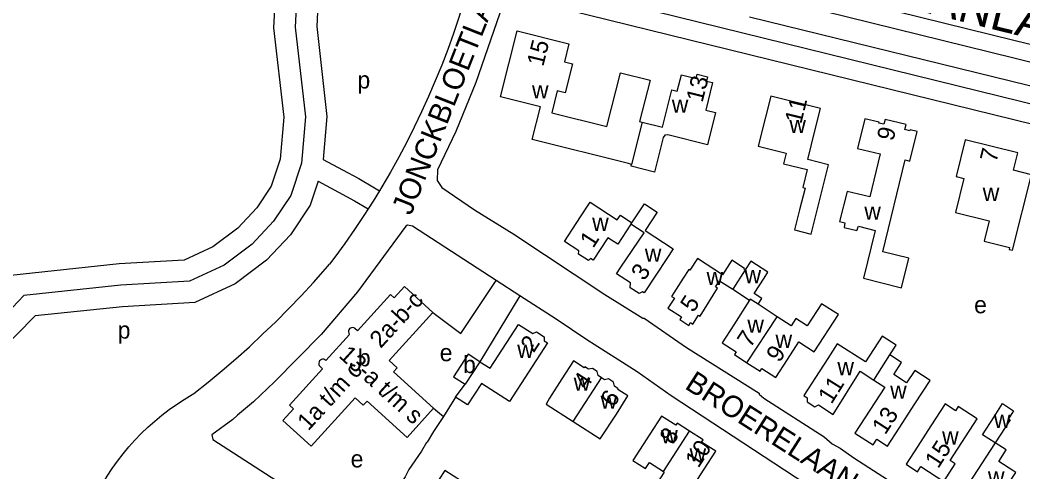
# Model space of a CAD drawing. Extents: x 161141 to 163125, y 381621 to 383200.
# Drawn here: x 161268.8 to 161502.1, y 382076.1 to 382181.3 of the extents above; entities that cross this region are included whole.
import ezdxf

# ---------------------------------------------------------------- set-up
doc = ezdxf.new("R2010")
doc.units = 0
for name, color, linetype in [('BLT_Basislijn', 7, 'Continuous'), ('BLT_Bebouwing', 7, 'Continuous'), ('BLT_Centroide', 7, 'Continuous'), ('BLT_Huisnummer', 7, 'Continuous'), ('BLT_Huisnummer_reeks', 7, 'Continuous'), ('BLT_Onderverdeling_panden', 7, 'Continuous'), ('BLT_Straatnaam', 7, 'Continuous'), ('BLT_Straatnaam_hoofdweg', 7, 'Continuous')]:
    doc.layers.add(name, color=color, linetype=linetype)

msp = doc.modelspace()

# ---------------------------------------------------------------- linework, layer by layer
at = {"layer": 'BLT_Basislijn'}
for p, q in [((161577.61, 382147.74), (161438.48, 382181.99)), ((161385.09, 382117.09), (161379.56, 382120.67)), ((161385.09, 382117.09), (161375.76, 382101.74)), ((161272.27, 382112.38), (161255.91, 382095.79)), ((161370.1, 382093.47), (161367.31, 382089)), ((161364.97, 382090.89), (161367.31, 382089))]:
    msp.add_line(p, q, dxfattribs=at)
for points in [[(161342.07, 382215.1), (161335.39, 382206.7), (161328.71, 382198.33), (161328.71, 382198.33), (161327.75, 382179.45), (161330.12, 382158.69), (161329.28, 382148.93), (161327.22, 382142.63), (161323.82, 382137.55), (161319.42, 382132.85), (161313.65, 382128.5), (161306.97, 382125.4), (161291.79, 382124.52), (161261.51, 382121.28)], [(161575.91, 382159.3), (161574.79, 382159.38), (161572.09, 382159.65), (161569.4, 382159.99), (161566.73, 382160.42), (161564.06, 382160.92), (161561.42, 382161.5), (161558.79, 382162.16), (161558.23, 382162.31), (161500, 382176.55), (161440.48, 382191.25), (161423.98, 382195.51), (161417.63, 382197.28)], [(161416.7, 382193.12), (161425.52, 382190.9), (161439.31, 382187.51), (161500, 382172.47), (161560.84, 382157.4), (161561.46, 382157.23), (161564.86, 382156.37), (161568.29, 382155.59), (161571.73, 382154.88), (161575.19, 382154.26), (161575.32, 382154.24)], [(161333.31, 382190.25), (161332.76, 382179.6), (161335.14, 382158.76), (161334.21, 382147.93), (161331.76, 382140.42), (161327.75, 382134.43), (161322.78, 382129.11), (161316.24, 382124.19), (161308.21, 382120.47), (161292.2, 382119.53), (161269.67, 382117.13)], [(161571.87, 382145), (161411.72, 382184.47), (161385.01, 382191.48)], [(161338.21, 382188.31), (161337.78, 382179.76), (161340.17, 382158.83), (161339.31, 382148.78)], [(161372.97, 382188.8), (161372.06, 382185.67), (161370.88, 382181.91), (161369.62, 382178.17), (161368.28, 382174.46), (161366.87, 382170.78), (161365.39, 382167.13), (161363.83, 382163.5), (161362.2, 382159.91), (161360.49, 382156.36), (161358.72, 382152.83), (161356.87, 382149.35), (161354.96, 382145.9), (161352.97, 382142.49), (161352.4, 382141.56)], [(161382.01, 382187.19), (161381.71, 382186.78), (161374.84, 382166.75), (161370.17, 382155.35), (161365.86, 382146.45), (161365.8, 382143.9), (161366.88, 382142.33), (161374.51, 382137.13), (161383.63, 382131.44), (161404.83, 382117.4), (161413.7, 382111.85), (161413.96, 382111.85), (161423.8, 382105.03), (161440.74, 382094.38), (161440.77, 382094.15), (161441.8, 382093.21), (161455.89, 382084.27), (161457.77, 382082.61), (161459.58, 382081.61), (161462.78, 382079.32), (161507, 382050.9), (161516.84, 382044.29), (161522.29, 382040.94)], [(161574.59, 382121.57), (161578.68, 382127.76), (161579.74, 382129.89), (161580.44, 382131.88), (161580.51, 382133.62), (161580.11, 382135.93), (161578.32, 382138.29), (161575.39, 382139.5), (161382.01, 382187.19)], [(161339.31, 382148.78), (161343.81, 382146.41), (161347.56, 382144.36), (161351.27, 382142.23), (161352.4, 382141.56)], [(161338.12, 382143.77), (161336.3, 382138.21), (161331.68, 382131.31), (161326.13, 382125.38), (161318.82, 382119.88), (161309.45, 382115.53), (161292.62, 382114.55), (161272.27, 382112.38)], [(161338.12, 382143.77), (161342.86, 382141.24), (161346.56, 382139.18), (161349.76, 382137.32)], [(161352.4, 382141.56), (161350.91, 382139.13), (161349.76, 382137.32)], [(161349.76, 382137.32), (161348.79, 382135.8), (161346.6, 382132.53), (161344.34, 382129.29), (161342.02, 382126.1), (161340.75, 382124.41)], [(161379.56, 382120.67), (161360.06, 382133.28), (161358.94, 382133.49), (161358.53, 382133.33), (161347.3, 382118.04), (161338.82, 382108.04), (161327.96, 382097.02), (161323.1, 382092.36), (161319.32, 382089.32), (161318.3, 382088.27), (161313.4, 382084.74), (161313.61, 382083.66), (161349.27, 382060.57)], [(161309.2, 382094.31), (161312.5, 382096.95), (161315.76, 382099.65), (161318.96, 382102.41), (161322.11, 382105.23), (161325.21, 382108.11), (161328.25, 382111.05), (161331.23, 382114.04), (161334.16, 382117.09), (161337.03, 382120.2), (161339.84, 382123.36), (161340.75, 382124.41)], [(161364.82, 382113.19), (161371.3, 382108.27), (161379.56, 382120.67)], [(161236.17, 382083.91), (161251.11, 382097.62), (161269.67, 382117.13)], [(161453.83, 382071.76), (161420.3, 382093.8), (161412.36, 382099.41), (161400.64, 382106.81), (161393.49, 382111.68), (161385.09, 382117.09)], [(161286.9, 382071.36), (161287.93, 382073.23), (161289.02, 382075.05), (161290.19, 382076.84), (161291.42, 382078.58), (161292.72, 382080.27), (161294.07, 382081.91), (161295.49, 382083.49), (161296.97, 382085.03), (161298.51, 382086.5), (161300.09, 382087.92), (161301.73, 382089.28), (161303.43, 382090.58), (161305.16, 382091.8), (161306.95, 382092.97), (161308.77, 382094.07), (161309.2, 382094.31)], [(161367.31, 382089), (161364.93, 382085.46), (161363.52, 382082.99), (161363.34, 382082.95), (161362.14, 382080.87), (161359.24, 382076.64), (161358.38, 382074.95), (161351.69, 382064.82), (161349.27, 382060.57)]]:
    msp.add_lwpolyline(points, dxfattribs=at)
at = {"layer": 'BLT_Bebouwing'}
for p, q in [((161380.56, 382163.42), (161384.41, 382178.79)), ((161384.41, 382178.79), (161396.49, 382175.75)), ((161396.49, 382175.75), (161395.44, 382171.57)), ((161395.44, 382171.57), (161397.31, 382171.09)), ((161397.31, 382171.09), (161395.63, 382164.36)), ((161405.33, 382156.47), (161408.49, 382169)), ((161408.49, 382169), (161415.35, 382167.3)), ((161393.77, 382164.83), (161392.48, 382159.66)), ((161395.63, 382164.36), (161393.77, 382164.83)), ((161389.84, 382161.08), (161380.56, 382163.42)), ((161387.93, 382153.49), (161389.84, 382161.08)), ((161392.48, 382159.66), (161405.33, 382156.47)), ((161413.55, 382157.51), (161418.26, 382156.31)), ((161434.58, 382118.61), (161438.51, 382116.05)), ((161437.91, 382101.5), (161444.92, 382112.21)), ((161345.44, 382108.09), (161339.92, 382102.02)), ((161373.04, 382103.5), (161369.63, 382098.24)), ((161375.76, 382101.74), (161373.04, 382103.5)), ((161369.63, 382098.24), (161372.35, 382096.48)), ((161370.1, 382093.47), (161372.35, 382096.48))]:
    msp.add_line(p, q, dxfattribs=at)
for points in [[(161415.35, 382167.3), (161412.87, 382157.68), (161413.55, 382157.51)], [(161418.26, 382156.31), (161420.44, 382165.05), (161421.69, 382164.73), (161422.65, 382168.56), (161426.09, 382167.71), (161426.33, 382168.67), (161428.73, 382168.07), (161428.48, 382167.07), (161429.91, 382166.71), (161428.32, 382160.3)], [(161451.93, 382146.47), (161450.89, 382142.29), (161451.42, 382142.16), (161450.16, 382137.07), (161449, 382132.43), (161452.88, 382131.46), (161454.04, 382136.11), (161456.89, 382147.58), (161452.05, 382148.78), (161453.81, 382155.83), (161455.01, 382160.68), (161443.43, 382163.56), (161442.23, 382158.71), (161440.53, 382151.89), (161447.05, 382150.27), (161446.44, 382147.84), (161451.93, 382146.47)], [(161428.32, 382160.3), (161430.61, 382159.73), (161428.75, 382152.27), (161419.47, 382154.58), (161418.81, 382154.48), (161418.41, 382153.95), (161416.36, 382145.89), (161410.94, 382147.27), (161411.05, 382147.69)], [(161411.05, 382147.69), (161410.33, 382147.87), (161387.93, 382153.49)], [(161400.66, 382137.73), (161401.39, 382138.86), (161407.74, 382134.76), (161408.45, 382135.86), (161411.15, 382134.11)], [(161411.15, 382134.11), (161414.04, 382138.51), (161417.04, 382136.54), (161414.25, 382132.3), (161420.74, 382128.04), (161419.26, 382125.79), (161416.71, 382121.92), (161413.96, 382117.74), (161413.58, 382117.99), (161412.8, 382117.59), (161410.72, 382118.93), (161410.78, 382120.09), (161407.53, 382122.2), (161408.57, 382123.78), (161413.96, 382131.76), (161410.91, 382133.74)], [(161410.91, 382133.74), (161407.89, 382129.07), (161405.52, 382130.61), (161402.14, 382125.37), (161401.53, 382125.76), (161401, 382125.32), (161398.74, 382126.77), (161398.78, 382127.58), (161395.48, 382129.72), (161398.19, 382133.91), (161400.66, 382137.73)], [(161437.48, 382123.1), (161437.25, 382123.25), (161437.37, 382123.43), (161434.42, 382125.35), (161432.23, 382121.98), (161426.41, 382125.76), (161424.65, 382123.04), (161424.37, 382123.22), (161423.03, 382121.15), (161420.31, 382116.95), (161421.01, 382116.5), (161419.52, 382114.2), (161422.68, 382112.16), (161422.28, 382111.54), (161424.38, 382110.18), (161424.8, 382110.83)], [(161440.48, 382115.13), (161441.36, 382116.49), (161439.55, 382117.64), (161441.89, 382121.21), (161442.79, 382122.57), (161438.84, 382125.16), (161437.48, 382123.1)], [(161424.8, 382110.83), (161425.3, 382110.51), (161426.63, 382112.57), (161427, 382112.34), (161431.07, 382118.89), (161430.62, 382119.18), (161431.54, 382120.59), (161434.58, 382118.61)], [(161364.82, 382113.19), (161358.18, 382119.23), (161355.81, 382116.62), (161354.96, 382117.4), (161347.25, 382108.94), (161346.68, 382109.46)], [(161438.51, 382116.05), (161434.82, 382110.35), (161432.1, 382106.15), (161435.39, 382104.03), (161434.98, 382103.4), (161437.91, 382101.5)], [(161437.91, 382101.5), (161440.95, 382099.53), (161441.37, 382100.17), (161444.64, 382098.05), (161447.35, 382102.25), (161450, 382106.35), (161453.56, 382104.04), (161459.17, 382112.71), (161455.28, 382115.23), (161451.95, 382110.09), (161449.3, 382111.8), (161448.2, 382110.09), (161444.92, 382112.21)], [(161364.97, 382090.89), (161355.65, 382099.38), (161356.52, 382100.34), (161354.66, 382102.03), (161364.82, 382113.19)], [(161444.92, 382112.21), (161440.48, 382115.13)], [(161346.68, 382109.46), (161346.45, 382109.6), (161346.19, 382109.67), (161345.92, 382109.66), (161345.66, 382109.57), (161345.44, 382109.41), (161345.28, 382109.19), (161345.18, 382108.94), (161345.17, 382108.67), (161345.23, 382108.4), (161345.37, 382108.17), (161345.44, 382108.09)], [(161375.76, 382101.74), (161378.12, 382100.21), (161384.73, 382110.43), (161388.05, 382108.29), (161388.91, 382108.72), (161390.75, 382107.53), (161390.71, 382106.59), (161391.46, 382106.1), (161382.64, 382092.46), (161376.12, 382096.67), (161372.87, 382091.68), (161370.1, 382093.47)], [(161471.14, 382103.3), (161472.62, 382105.59), (161469.37, 382107.7), (161465.47, 382101.68), (161458.91, 382105.92), (161456.74, 382102.52), (161453.86, 382098.07), (161451.14, 382093.87), (161451.95, 382093.35), (161451.9, 382092.38), (161453.69, 382091.23), (161454.57, 382091.68), (161458, 382089.46), (161464.27, 382099.5), (161467.46, 382097.44)], [(161339.92, 382102.02), (161339.69, 382102.19), (161339.43, 382102.29), (161339.16, 382102.31), (161338.89, 382102.24), (161338.64, 382102.11), (161338.45, 382101.91), (161338.32, 382101.67), (161338.26, 382101.4), (161338.29, 382101.12), (161338.39, 382100.86), (161338.56, 382100.64), (161338.62, 382100.59)], [(161404.03, 382098), (161403.25, 382098.51), (161403.05, 382099.46), (161401.95, 382100.16), (161401.03, 382099.97), (161400.18, 382100.51), (161400.05, 382100.31), (161397.58, 382101.91), (161394.86, 382097.71), (161391.97, 382093.24), (161391.15, 382091.88), (161397.44, 382087.81)], [(161472.09, 382098.77), (161473.88, 382101.53), (161471.14, 382103.3)], [(161338.62, 382100.59), (161339.16, 382100.1), (161331.46, 382091.64), (161332.4, 382090.78), (161329.93, 382088.06), (161336.5, 382082.08), (161346.73, 382093.32), (161348.62, 382091.6), (161349.52, 382092.58), (161358.81, 382084.12), (161364.97, 382090.89)], [(161476.99, 382091.9), (161480.54, 382097.39), (161476.94, 382099.72), (161475.06, 382096.85), (161472.09, 382098.77)], [(161397.44, 382087.81), (161403.74, 382083.74), (161407.51, 382089.56), (161410.22, 382093.76), (161407.86, 382095.29), (161407.96, 382095.45), (161407.08, 382096.01), (161406.88, 382096.98), (161405.71, 382097.73), (161404.76, 382097.53), (161404.03, 382098)], [(161467.46, 382097.44), (161469.97, 382095.82), (161463.02, 382085.09), (161467.26, 382082.35), (161468.12, 382083.67), (161470.62, 382082.05), (161473.33, 382086.25), (161476.99, 382091.9)], [(161486.34, 382077.98), (161485.17, 382078.74), (161491.47, 382088.47), (161487.09, 382091.3), (161486.45, 382090.31), (161484.01, 382091.89), (161480.72, 382086.8), (161477.65, 382082.05), (161474.94, 382077.86), (161477.6, 382076.13), (161478.36, 382077.32), (161483.68, 382073.88), (161486.34, 382077.98)], [(161495.63, 382082.81), (161492.69, 382084.71), (161495.41, 382088.91), (161497.4, 382091.98), (161499.96, 382090.33), (161498.75, 382088.47), (161499.14, 382088.22), (161495.63, 382082.81)], [(161424.55, 382085.57), (161421.66, 382087.44), (161421.33, 382086.93), (161417.99, 382089.08), (161415.28, 382084.88), (161411.32, 382078.76), (161414.28, 382076.85), (161415.2, 382078.28), (161418.47, 382076.16)], [(161418.47, 382076.16), (161418.67, 382076.03), (161416.79, 382073.12), (161420.43, 382070.77), (161421.39, 382072.24), (161423.96, 382070.58), (161427.92, 382076.72), (161430.64, 382080.91), (161427.36, 382083.03), (161427.69, 382083.54), (161424.55, 382085.57)], [(161495.63, 382082.81), (161487.46, 382070.19), (161489.15, 382069.1), (161488.59, 382068.24), (161491.97, 382066.05), (161492.53, 382066.91), (161494.02, 382065.95), (161495.82, 382068.73), (161499.53, 382066.33), (161502.11, 382070.32), (161498.4, 382072.72)], [(161498.4, 382072.72), (161500.01, 382075.21), (161500.5, 382075.96), (161500, 382076.28), (161496.53, 382078.53), (161498.25, 382081.18), (161495.63, 382082.81)], [(161373.41, 382072.66), (161367.59, 382076.44), (161363.62, 382070.32), (161360.26, 382072.5), (161357.18, 382067.74), (161354.46, 382063.54), (161355.18, 382063.09), (161354.95, 382062.73), (161357.17, 382061.29), (161357.4, 382061.64), (161361.19, 382059.19), (161367.03, 382068.19), (161367.61, 382067.81), (161368.3, 382068.88), (161370.16, 382067.67)]]:
    msp.add_lwpolyline(points, dxfattribs=at)
for points in [[(161474.95, 382156.97), (161470.06, 382158.17), (161469.78, 382157.02), (161468.61, 382157.28), (161468.66, 382157.51), (161465.34, 382158.28), (161463.64, 382151.4), (161468.93, 382150.1), (161466.49, 382140.1), (161461.19, 382141.34), (161459.47, 382134.35), (161460.66, 382134.06), (161460.54, 382133.02), (161463.51, 382132.29), (161463.89, 382133.27), (161467.74, 382132.32), (161464.99, 382121.15), (161473.9, 382118.95), (161475.6, 382125.83), (161469.54, 382127.32), (161474.75, 382148.71), (161475.83, 382148.44), (161477.5, 382155.33), (161475.89, 382155.74), (161475.83, 382155.53), (161474.66, 382155.8)], [(161500.92, 382150.39), (161488.7, 382153.43), (161486.57, 382144.83), (161488.4, 382144.38), (161486.43, 382136.45), (161494.25, 382134.5), (161493.09, 382129.81), (161499.02, 382128.34), (161498.94, 382127.87), (161499.71, 382127.68), (161504.09, 382145.27), (161499.9, 382146.3)]]:
    msp.add_lwpolyline(points, close=True, dxfattribs=at)
at = {"layer": 'BLT_Onderverdeling_panden'}
for p, q in [((161413.55, 382157.51), (161411.05, 382147.69)), ((161410.91, 382133.74), (161411.15, 382134.11)), ((161437.48, 382123.1), (161434.58, 382118.61)), ((161375.76, 382101.74), (161372.35, 382096.48)), ((161467.46, 382097.44), (161471.14, 382103.3)), ((161397.44, 382087.81), (161404.03, 382098)), ((161418.47, 382076.16), (161424.55, 382085.57))]:
    msp.add_line(p, q, dxfattribs=at)
msp.add_lwpolyline([(161440.48, 382115.13), (161438.68, 382116.31), (161438.51, 382116.05)], dxfattribs=at)

# ---------------------------------------------------------------- texts
at = {"layer": 'BLT_Centroide'}
for s, p in [('p', (161347.27, 382165.35)), ('w', (161387.88, 382163.03)), ('w', (161420.41, 382159.7)), ('w', (161447.77, 382154.98)), ('w', (161492.77, 382139.15)), ('w', (161465.21, 382134.8)), ('w', (161401.88, 382132.2)), ('w', (161414.14, 382125)), ('w', (161428.5, 382119.58)), ('w', (161437.34, 382120.02)), ('e', (161490.77, 382113.01)), ('w', (161438, 382108.47)), ('p', (161291.47, 382107.11)), ('w', (161444.55, 382104.94)), ('b', (161347.36, 382100.66)), ('e', (161366.41, 382101.85)), ('w', (161384.45, 382102.62)), ('b', (161371.84, 382099.09)), ('w', (161458.95, 382098.59)), ('w', (161397.59, 382094.97)), ('w', (161471.22, 382093.12)), ('w', (161403.83, 382090.78)), ('w', (161495.36, 382086.3)), ('w', (161417.94, 382082.75)), ('w', (161483.31, 382082.45)), ('e', (161345.68, 382077.12)), ('w', (161424.55, 382078.53)), ('w', (161493.98, 382073.11))]:
    msp.add_text(s, height=4, dxfattribs=at).set_placement(p)
at = {"layer": 'BLT_Huisnummer'}
for s, rotation, p in [('15', 76.0419, (161390.49, 382170.31)), ('13', 76.0105, (161427.56, 382161.94)), ('11', 76.0235, (161450.52, 382156.94)), ('9', 76.0266, (161471.94, 382152.95)), ('7', 76.0145, (161495.92, 382147.97)), ('1', 57.1601, (161402.11, 382127.98)), ('3', 56.6528, (161414, 382120.38)), ('5', 57.0826, (161425.46, 382113)), ('7', 57.0889, (161438.71, 382104.78)), ('2', 57.1174, (161388.28, 382103.65)), ('9', 57.0982, (161445.46, 382101.34)), ('4', 57.1176, (161400.56, 382095.1)), ('11', 57.9844, (161457.57, 382091.68)), ('6', 57.1164, (161406.92, 382090.96)), ('13', 57.0943, (161470.08, 382084.53)), ('8', 57.1223, (161420.64, 382082.21)), ('10', 57.1196, (161426.6, 382076.81)), ('15', 57.0924, (161482.4, 382076.68))]:
    msp.add_text(s, height=4, rotation=rotation, dxfattribs=at).set_placement(p)
at = {"layer": 'BLT_Huisnummer_reeks'}
for s, rotation, p in [('2a-b-c', 47.6868, (161352.67, 382104.68)), ('13-a t/m s', 317.6868, (161342.72, 382102.93)), ('1a t/m c', 47.6868, (161335.83, 382085.48))]:
    msp.add_text(s, height=4, rotation=rotation, dxfattribs=at).set_placement(p)
at = {"layer": 'BLT_Straatnaam'}
for s, rotation, p in [('JONCKBLOETLAAN', 68.4563, (161359.75, 382135.61)), ('BROERELAAN', 327.3398, (161423.19, 382095.64))]:
    msp.add_text(s, height=5, rotation=rotation, dxfattribs=at).set_placement(p)
at = {"layer": 'BLT_Straatnaam_hoofdweg'}
msp.add_text('DR SCHAEPMANLAAN', height=8, rotation=346.1097, dxfattribs=at).set_placement((161410.43, 382200.08))

doc.saveas('drawing.dxf')
